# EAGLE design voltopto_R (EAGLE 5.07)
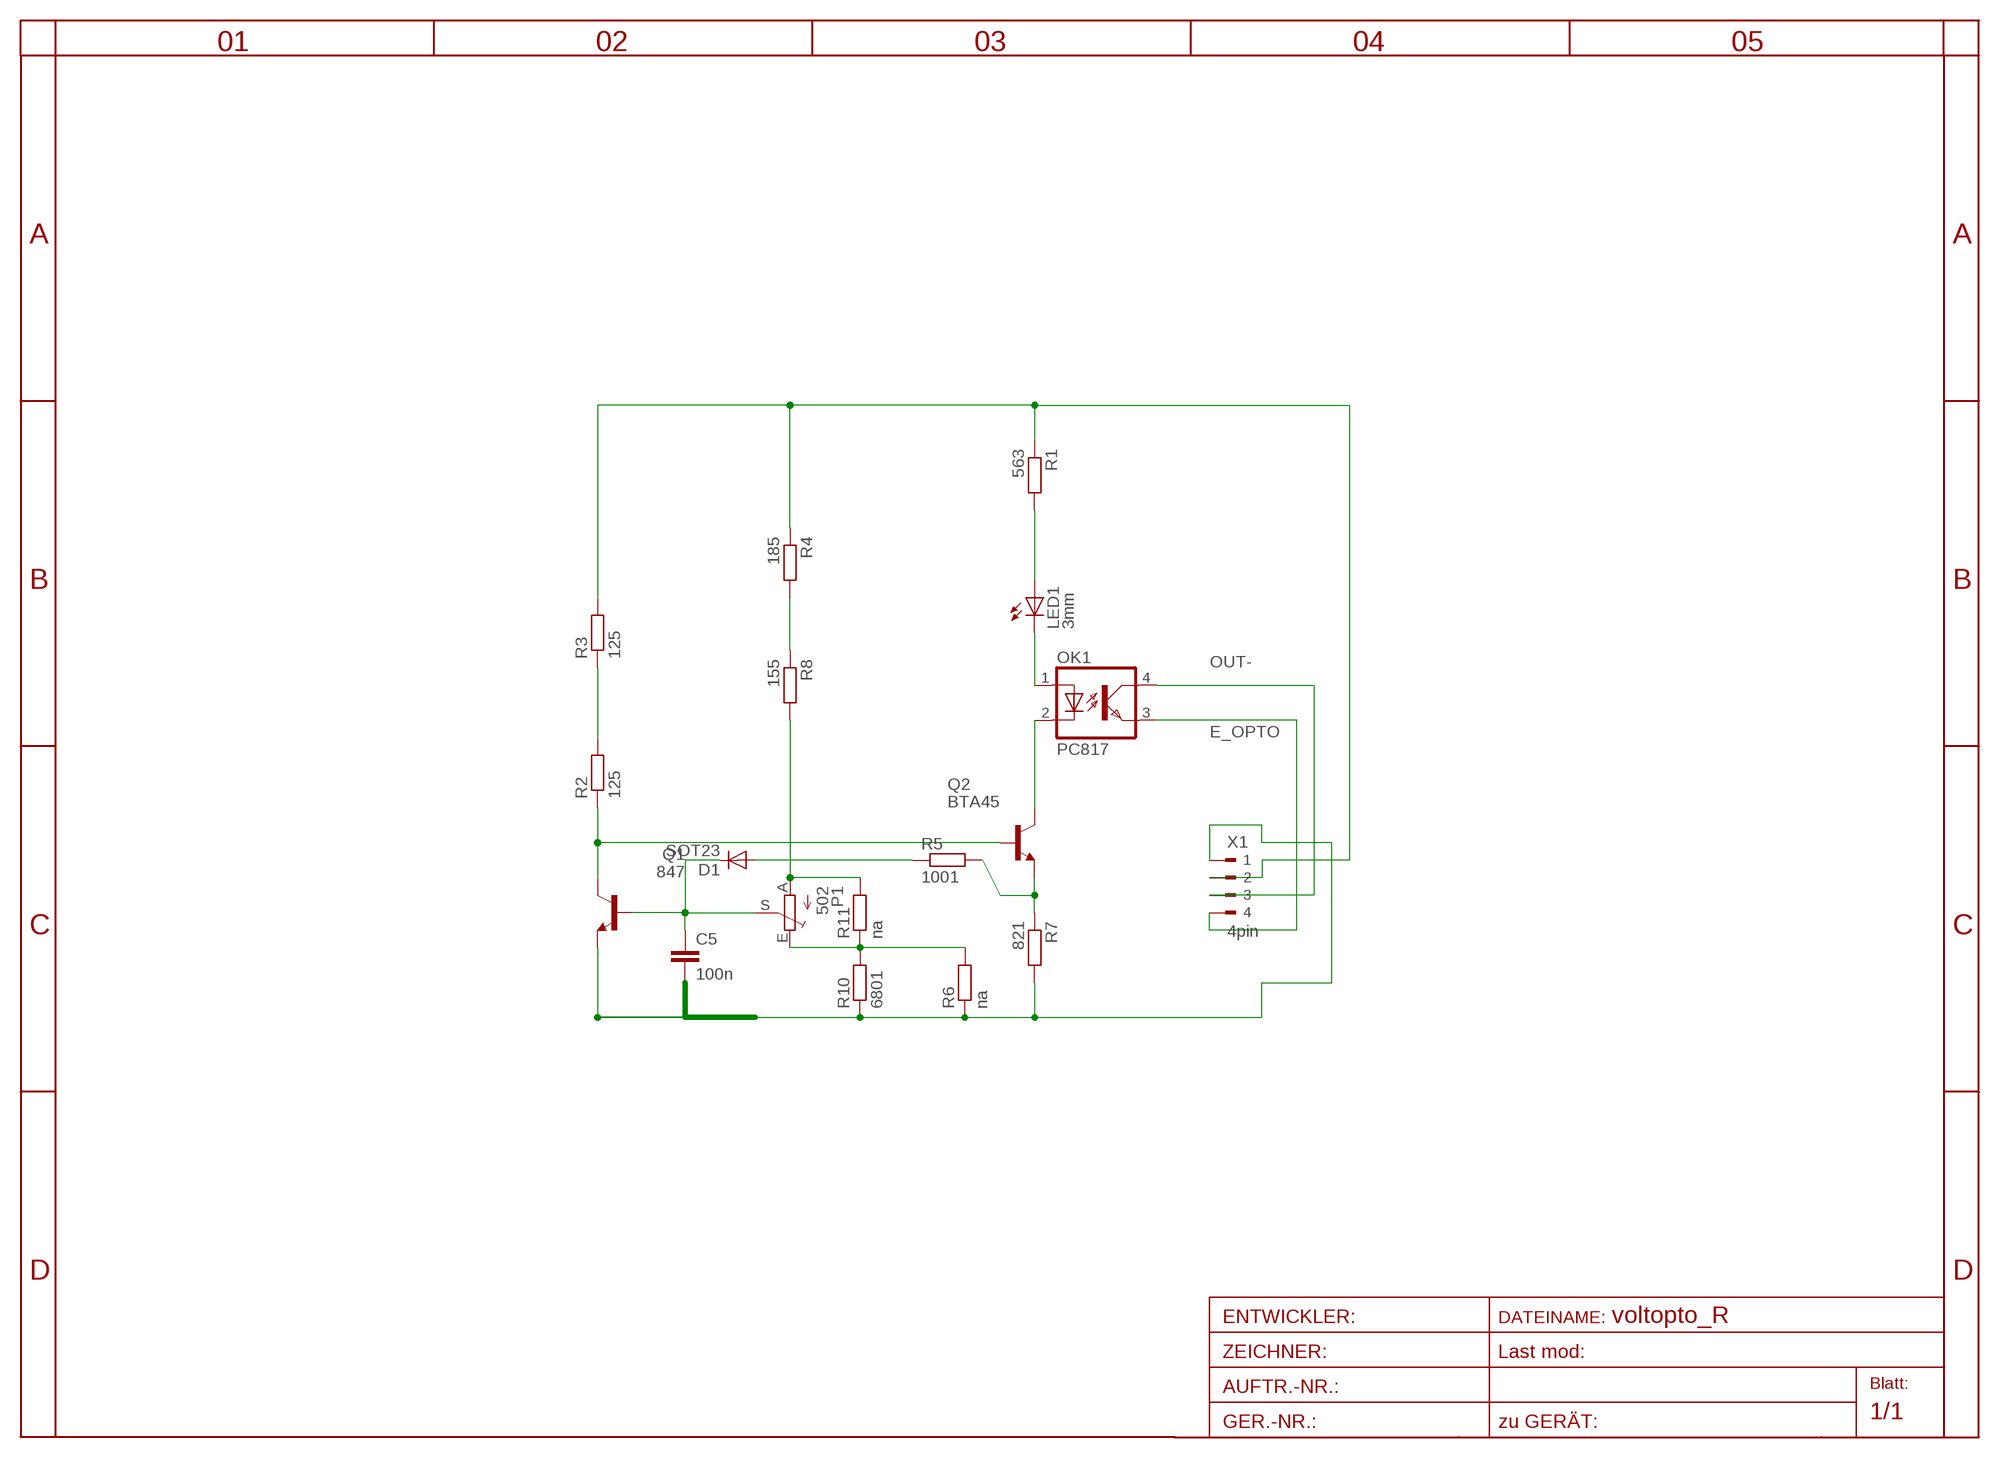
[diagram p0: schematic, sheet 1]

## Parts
C5  100n  C-EUC0805  [C0805]
D1  SOT23  DIODE-SOT23  [SOT23]
LED1  3mm  LED5MM  [LED5MM]
OK1  PC817  [DIL04]
P1  502  TRIM_EU-S64W  [S64W]
Q1  847  SMBTA45HV  [SOT23HV]
Q2  BTA45  SMBTA45HV  [SOT23HV]
R1  563  R-EU_R1206  [R1206]
R2  125  R-EU_R1206  [R1206]
R3  125  R-EU_R1206  [R1206]
R4  185  R-EU_R1206  [R1206]
R5  1001  R-EU_R1206  [R1206]
R6  na  R-EU_R0805  [R0805]
R7  821  R-EU_R1206  [R1206]
R8  155  R-EU_R1206  [R1206]
R10  6801  R-EU_R0805  [R0805]
R11  na  R-EU_R1206  [R1206]
X1  4pin  90-4  [90-4]

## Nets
A: LED1.A R1.2
A1: P1.A R8.2 R11.2
E1: P1.E R6.2 R10.2 R11.1
E_OPTO: OK1.3(EMIT) X1.4
IN: R1.1 R3.2 R4.1 X1.2
K: LED1.K(C) OK1.1(A)
N$3: R2.2 R3.1
N$6: D1.1(A) R5.1
N$8: Q2.2(E) R5.2 R7.1
N$13: R4.2 R8.1
N$20: Q1.3(C) Q2.1(B) R2.1
N$21: OK1.2(C) Q2.3(C)
OUT-: OK1.4(COL) X1.3
S: C5.1 D1.3(C) P1.S Q1.1(B)
V-: C5.2 Q1.2(E) R6.1 R7.2 R10.1 X1.1

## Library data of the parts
C5 = rcl:C-EU: CAPACITOR, European symbol
D1 = diode:DIODE-: DIODE
LED1 = led:LED: LED
OK1 = optocoupler:PC817: SHARP OPTO COUPLER
P1 = pot:TRIM_EU-: POTENTIOMETER
Q1 Q2 = transistor-npn:SMBTA45
R1-R8 R10 R11 = rcl:R-EU_: RESISTOR, European symbol
X1 = con-weidmueller-sl35:90-4: WEIDMUELLER CLAMP CONNECTOR

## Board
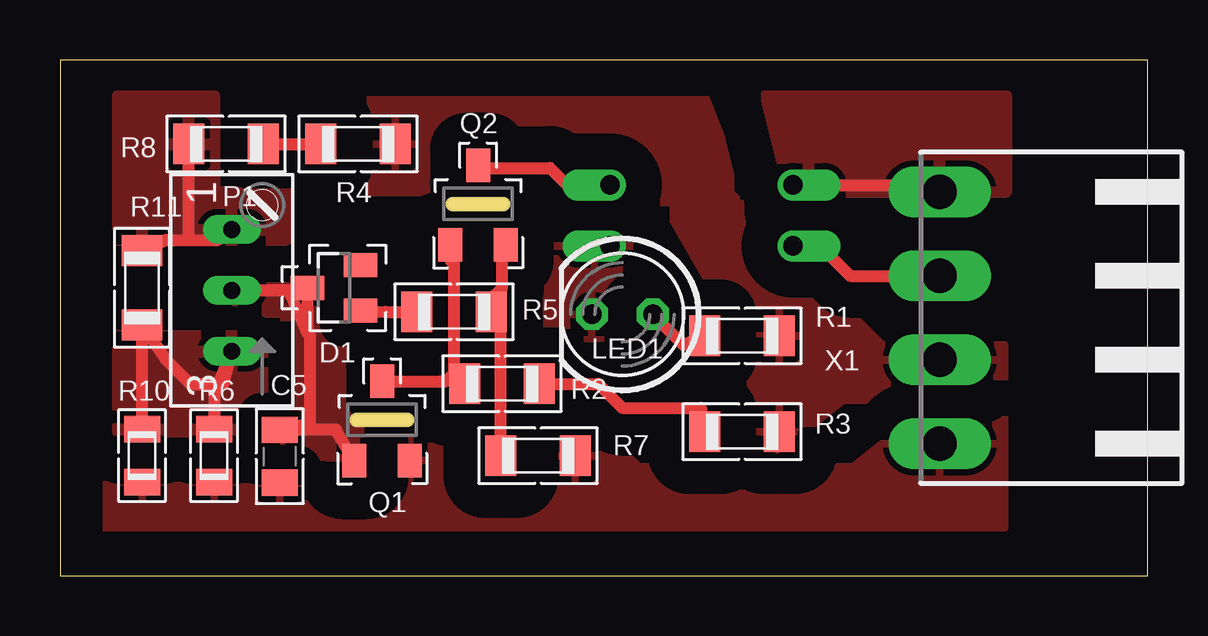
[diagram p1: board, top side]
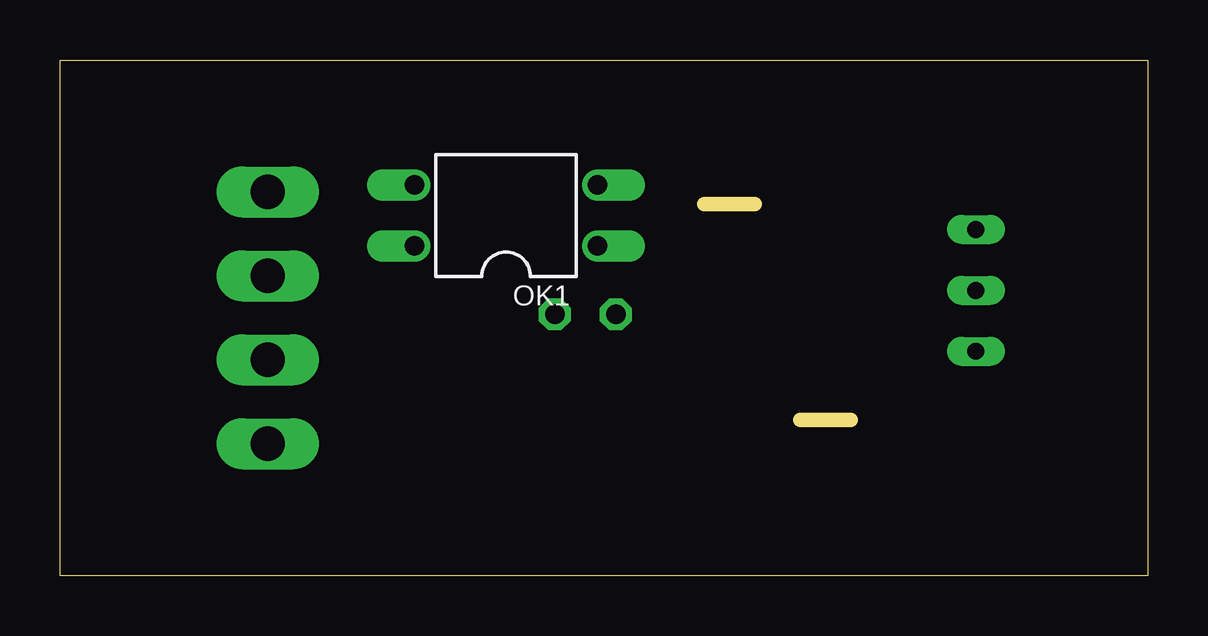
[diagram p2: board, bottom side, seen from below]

Size 45.32 x 21.5 mm. Coordinates in mm from the lower left corner, seen from the top.
Outline: 0,0 45.32,0 45.32,21.5 0,21.5 0,0
Copper layers (1*16): Top 0.035mm / dielectric 1.5mm / Bottom 0.035mm
Design rules "default *": minimum track width 10mil, minimum drill 20mil, track to track 8mil, track to pad 8mil, pad to pad 8mil, via to via 8mil, smd to smd 8mil, copper to edge 40mil, drill to drill 8mil, minimum pad ring 10mil, minimum via ring 8mil, stop-mask expansion 4mil, vias tented up to drill 0mil, thermal gap 10mil

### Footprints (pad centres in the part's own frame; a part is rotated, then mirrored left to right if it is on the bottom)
C0805 = smd 1.1 x 1.5: 1 -1.1,0; 2 1.1,0
SOT23 = smd 1 x 1.4: 1 -0.95,-1.1; 2 0.95,-1.1; 3 0,1.1
LED5MM = drill 0.813 octagon: A -1.27,0; K 1.27,0
DIL04 = drill 0.813 offset: 1 -1.27,-3.81; 2 1.27,-3.81; 3 1.27,3.81; 4 -1.27,3.81
S64W = drill 0.7 long: A 2.54,1.27; E -2.54,1.27; S 0,1.27
SOT23HV = smd 1 x 1.4: 1 -1.15,-1.7; 2 1.15,-1.7; 3 0,1.6
R1206 = smd 1.3 x 1.7: 1 -1.55,0; 2 1.55,0
R0805 = smd 1.1 x 1.5: 1 -1.1,0; 2 1.1,0
90-4 = drill 1.422 long: 1 -5.25,5.25; 2 -1.75,5.25; 3 1.75,5.25; 4 5.25,5.25

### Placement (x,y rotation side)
C5  9.16,4.97 270 top
D1  11.42,12 90 top
LED1  23.43,10.89 180 top
OK1  26.73,15.02 90 bottom
P1  8.43,11.89 90 top
Q1  13.42,6.5 0 top
Q2  17.42,15.5 0 top
R1  28.42,10 180 top
R2  18.42,8 0 top
R3  28.42,6 0 top
R4  12.42,18 180 top
R5  16.42,11 0 top
R6  6.42,5 90 top
R7  19.92,5 0 top
R8  6.92,18 180 top
R10  3.42,5 90 top
R11  3.42,12 90 top
X1  41.91,10.75 90 top

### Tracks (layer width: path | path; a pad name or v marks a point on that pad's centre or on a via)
A
  Top 0.5: R1.2 25.97,9.62 LED1.A
A1
  Top 0.5: R11.2 4.42,14 5.42,14 | 5.42,14 6.59,14 P1.A | R8.2 5.37,14.05 5.42,14
  pour Top (isolate 1): 2.42,20 6.42,20 6.42,16 9.42,16 9.42,14 2.42,14
E1
  Top 0.5: R6.2 6.42,7.61 P1.E 6.81,8 5.42,8 4.42,9 R11.1 R10.2
  pour Top (isolate 1): 2.42,10 8.42,10 8.42,7 8.42,6 2.42,6
E_OPTO
  Top 0.5: OK1.3 36.37,16.29 X1.4
  pour Top (isolate 1): 29.42,20 39.42,20 39.42,19 39.42,16 30.42,16
IN
  pour Top (isolate 1.5, rank 2): 39.37,9.62 34.29,9.62 27.94,15.97 27.94,17.24 26.67,20.5 12.92,20.5 12.92,15.97 24.86,15.97 28.21,10.14 30.35,10 28.35,8.78 28.31,7.71 28.31,6.45 27.94,4.54 31.75,4.54 35.56,7.08 39.37,7.08
K
  pour Top (isolate 1.5): 19.05,13.43 20.32,14.7 23.11,14.7 23.75,14.06 23.75,12.03 23.3,11.59 23.3,9.49 22.8,8.98 20.07,8.98 18.99,10.06
N$3
  Top 0.5: R2.2 22.42,8 23.42,7 26.69,7 R3.1
N$6
  Top 0.5: R5.1 13.57,11 D1.1
N$8
  Top 0.5: R7.1 18.37,10.6 R5.2 17.97,11.55 18.42,12 18.42,13.15 Q2.2
N$13
  Top 0.5: R8.1 R4.2
N$20
  Top 0.5: 16.42,8.6 R2.1 16.42,8.45 | Q2.1 16.27,13.15 16.42,13 16.42,8.45 | Q1.3 16.07,8.1 16.42,8.45
N$21
  Top 0.5: OK1.2 21.13,16.29 20.42,17 17.82,17 Q2.3
OUT-
  Top 0.5: X1.3 32.92,12.5 31.42,14 30.8,14 OK1.4
S
  Top 0.5: Q1.1 11.5,6.07 C5.1 10.42,6.34 10.42,10 10.32,10.1 | P1.S 9.53,11.89 10.32,10.1 | 10.32,10.1 D1.3
  pour Top (isolate 1, rank 2): 7.42,12 12.42,12 12.42,5 9.42,5 9.42,11 7.42,11
V-
  pour Top (isolate 1.75): 1.35,4.54 1.35,2 39.37,2 39.37,6.57 35.56,6.57 33.02,4.54 24.13,4.54 22.86,5.81 13.97,5.81 13.97,4.54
